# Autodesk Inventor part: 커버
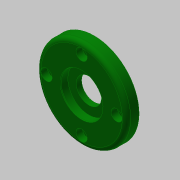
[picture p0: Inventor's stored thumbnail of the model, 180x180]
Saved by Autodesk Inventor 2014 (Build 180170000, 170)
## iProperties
Created: 2019-06
Part Number: 커버
Material: 알루미늄 6061
Document SubType Name: Modeling
Designer: mduedu
Density: 1 g/cm^3
Appearance: 진녹색
Author: mduedu
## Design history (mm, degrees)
sketch "스케치1"
  geometry: L1 (0, 0)-(9, 0); L2 (9, 0)-(9, 32); L3 (9, 32)-(0, 32); L4 (0, 32)-(0, 0); L5 (9, 0)-(12, 0); L6 (12, 0)-(12, 20); L7 (12, 20)-(9, 20); L8 (9, 20)-(9, 0)
  constraints: 16 end point, 4 parallel, 2 horizontal, 2 perpendicular
  dimensions: "d0" = 64 diameter of L3 L1; "d2" = 40 diameter of L7 L5; "d3" = 12 distance between parallel lines of L6 L4; "d4" = 3 distance between parallel lines of L2 L6
revolve "회전1" sketch "스케치1" stored, may be unused: angle "d5" = 90 deg
sketch "스케치2"
  geometry: L1 (0, 0)-(5.2, 0); L2 (5.2, 0)-(5.2, 15); L3 (5.2, 15)-(0, 15); L4 (0, 15)-(0, 0); L5 (5.2, 0)-(9, 0); L6 (9, 0)-(9, 9); L7 (9, 9)-(5.2, 9); L8 (5.2, 9)-(5.2, 0); L9 (9, 0)-(12, 0); L10 (12, 0)-(12, 15); L11 (12, 15)-(9, 15); L12 (9, 15)-(9, 0); L13 (12, -20)-(12, 20) reference
  constraints: 24 end point, 6 parallel, 3 horizontal, 3 perpendicular, 1 collinear
  dimensions: "d6" = 30 diameter of L3 L1; "d8" = 30 diameter of L11 L9; "d9" = 18 diameter of L7 L5; "d10" = 5.2 distance of L2.end L3.end; "d11" = 3 distance between parallel lines of L10 L12
revolve "회전2" sketch "스케치2" stored, may be unused: angle "d12" = 90 deg
fillet "모깎기1" dims "d13" = 3
fillet "모깎기2" dims "d14" = 3
chamfer "모따기1" distance "d15" = 1; stored, may be unused: second distance "d16" = 2, angle "d17" = 45 deg
sketch "스케치3" dims "d18" = 50
  geometry: 3 further points
  constraints: 2 vertical alignment, 1 coincident, 2 other
hole "구멍1" sketch "스케치3" at (0, 25) diameter "d19" = 4.5; stored, may be unused: countersink angle "d23" = 90 deg, drill point angle "d25" = 118 deg; dims "d20" = 6, "d21" = 8, "d22" = 4.6, "d24" = 8
chamfer "모따기2" distance "d29" = 0.5; stored, may be unused: second distance "d30" = 2, angle "d31" = 30 deg
node "솔리드1"
pattern_circular "원형 패턴1" dims angle "d27" = 360 deg
